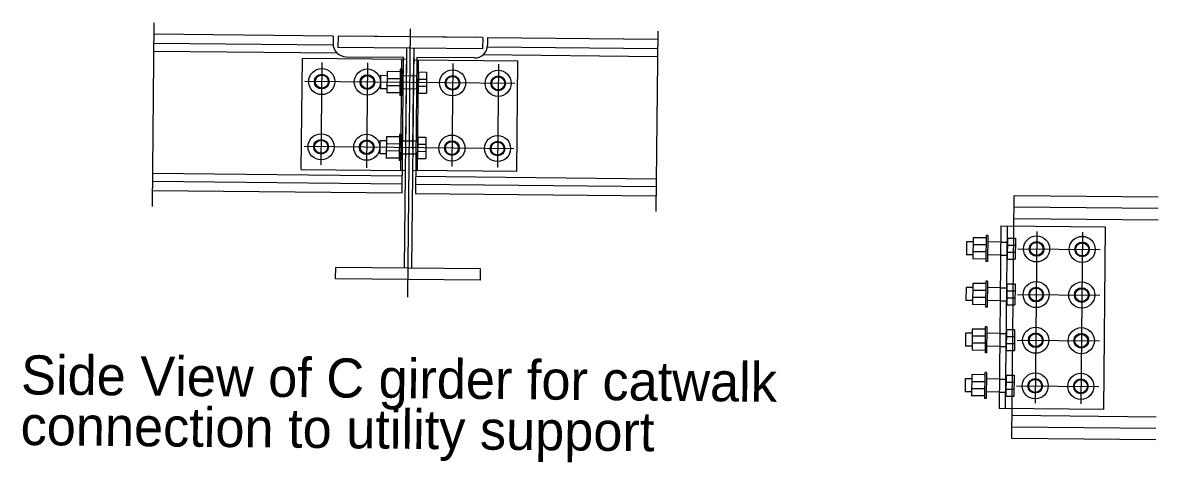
# Model space of a CAD drawing. Extents: x 632312 to 632885, y 378199 to 378534.
# Drawn here: x 632382.19 to 632389.45, y 378388.67 to 378391.48 of the extents above; entities that cross this region are included whole.
import ezdxf

# ---------------------------------------------------------------- set-up
doc = ezdxf.new("R2010")
doc.units = 0
for name, color, linetype in [('B_Boring', 7, 'Continuous'), ('R_Proposed Const Limits Cut', 7, 'Continuous'), ('R_Wall', 7, 'Continuous'), ('SHT_Dimensions', 7, 'Continuous'), ('USACE_Easement', 7, 'Continuous')]:
    doc.layers.add(name, color=color, linetype=linetype)

msp = doc.modelspace()

# ---------------------------------------------------------------- linework, layer by layer
at = {"layer": 'B_Boring'}
for p, q in [((632384.1753, 378391.3967), (632383.029, 378391.4081)), ((632384.1753, 378391.3967), (632384.1748, 378391.3488)), ((632384.2065, 378391.3964), (632384.2058, 378391.3239)), ((632385.1315, 378391.3872), (632384.2065, 378391.3964)), ((632385.1315, 378391.3872), (632385.1307, 378391.3147)), ((632385.1627, 378391.3869), (632385.1622, 378391.339)), ((632385.1627, 378391.3869), (632386.249, 378391.3761)), ((632384.1747, 378391.3384), (632383.0284, 378391.3498)), ((632385.1307, 378391.3147), (632384.2058, 378391.3239)), ((632384.632, 378389.9146), (632384.646, 378391.3195)), ((632384.6906, 378391.3191), (632384.6766, 378389.9141)), ((632385.1621, 378391.3286), (632386.2485, 378391.3178)), ((632383.9716, 378390.5445), (632383.9786, 378391.2528)), ((632384.6452, 378391.2462), (632383.9786, 378391.2528)), ((632384.2573, 378391.2646), (632384.6245, 378391.261)), ((632384.6069, 378390.5382), (632384.614, 378391.2465)), ((632384.6159, 378390.3923), (632384.6245, 378391.261)), ((632384.6898, 378391.2457), (632385.3565, 378391.2391)), ((632384.7108, 378391.2601), (632384.7022, 378390.3914)), ((632385.0781, 378391.2565), (632384.7108, 378391.2601)), ((632384.714, 378390.5371), (632384.7211, 378391.2454)), ((632385.3494, 378390.5308), (632385.3565, 378391.2391)), ((632384.5195, 378391.1693), (632384.5181, 378391.0339)), ((632384.6028, 378391.1685), (632384.5195, 378391.1693)), ((632384.6029, 378391.1841), (632384.6013, 378391.0175)), ((632384.6134, 378391.184), (632384.6029, 378391.1841)), ((632384.6134, 378391.184), (632384.6117, 378391.0173)), ((632384.7203, 378391.1673), (632384.7189, 378391.0319)), ((632384.7203, 378391.1673), (632384.7724, 378391.1668)), ((632384.7724, 378391.1668), (632384.771, 378391.0314)), ((632384.4775, 378391.1437), (632384.4767, 378391.0604)), ((632384.5192, 378391.1433), (632384.4775, 378391.1437)), ((632384.6023, 378391.1233), (632384.519, 378391.1242)), ((632384.7198, 378391.1222), (632384.7719, 378391.1217)), ((632384.5184, 378391.0599), (632384.4767, 378391.0604)), ((632384.6014, 378391.0331), (632384.5181, 378391.0339)), ((632384.6019, 378391.0782), (632384.5186, 378391.079)), ((632384.6117, 378391.0173), (632384.6013, 378391.0175)), ((632384.7189, 378391.0319), (632384.771, 378391.0314)), ((632384.7194, 378391.077), (632384.7715, 378391.0765)), ((632384.4734, 378390.727), (632384.4726, 378390.6437)), ((632384.5151, 378390.7266), (632384.4734, 378390.727)), ((632384.5153, 378390.7527), (632384.514, 378390.6173)), ((632384.5986, 378390.7518), (632384.5153, 378390.7527)), ((632384.5988, 378390.7675), (632384.5971, 378390.6008)), ((632384.6092, 378390.7674), (632384.5988, 378390.7675)), ((632384.6092, 378390.7674), (632384.6076, 378390.6007)), ((632384.7162, 378390.7507), (632384.7148, 378390.6153)), ((632384.7162, 378390.7507), (632384.7682, 378390.7501)), ((632384.7682, 378390.7501), (632384.7669, 378390.6148)), ((632384.5977, 378390.6616), (632384.5144, 378390.6624)), ((632384.5982, 378390.7067), (632384.5149, 378390.7075)), ((632384.7153, 378390.6604), (632384.7673, 378390.6599)), ((632384.7157, 378390.7055), (632384.7678, 378390.705)), ((632384.5142, 378390.6433), (632384.4726, 378390.6437)), ((632384.5973, 378390.6164), (632384.514, 378390.6173)), ((632384.6076, 378390.6007), (632384.5971, 378390.6008)), ((632384.7148, 378390.6153), (632384.7669, 378390.6148)), ((632383.9716, 378390.5445), (632384.6382, 378390.5379)), ((632385.3494, 378390.5308), (632384.6828, 378390.5375)), ((632384.6164, 378390.4506), (632383.0196, 378390.4665)), ((632384.7027, 378390.4497), (632386.2397, 378390.4345)), ((632384.6159, 378390.3923), (632383.019, 378390.4082)), ((632384.7022, 378390.3914), (632386.2391, 378390.3761)), ((632388.5133, 378388.8256), (632388.5287, 378390.3756)), ((632389.4491, 378390.3664), (632388.5287, 378390.3756)), ((632389.4483, 378390.2939), (632388.528, 378390.3031)), ((632388.4435, 378390.1847), (632388.4319, 378389.0181)), ((632388.4435, 378390.1847), (632389.1101, 378390.1781)), ((632388.4735, 378389.0177), (632388.4851, 378390.1843)), ((632389.1101, 378390.1781), (632389.0985, 378389.0115)), ((632388.2237, 378390.0828), (632388.2229, 378389.9994)), ((632388.2654, 378390.0823), (632388.2237, 378390.0828)), ((632388.2656, 378390.1084), (632388.2643, 378389.973)), ((632388.349, 378390.1075), (632388.2656, 378390.1084)), ((632388.3491, 378390.1232), (632388.3475, 378389.9565)), ((632388.3595, 378390.1231), (632388.3491, 378390.1232)), ((632388.3595, 378390.1231), (632388.3579, 378389.9564)), ((632388.4424, 378390.0806), (632388.3591, 378390.0814)), ((632388.4844, 378390.1062), (632388.5364, 378390.1057)), ((632388.5364, 378390.1057), (632388.5351, 378389.9703)), ((632388.2645, 378389.999), (632388.2229, 378389.9994)), ((632388.3481, 378390.0173), (632388.2647, 378390.0181)), ((632388.3485, 378390.0624), (632388.2652, 378390.0632)), ((632388.4416, 378389.9973), (632388.3583, 378389.9981)), ((632388.4835, 378390.0159), (632388.5356, 378390.0154)), ((632388.4839, 378390.0611), (632388.536, 378390.0606)), ((632388.3476, 378389.9722), (632388.2643, 378389.973)), ((632388.3579, 378389.9564), (632388.3475, 378389.9565)), ((632388.483, 378389.9708), (632388.5351, 378389.9703)), ((632384.1911, 378389.8465), (632384.1918, 378389.919)), ((632385.1168, 378389.9098), (632384.1918, 378389.919)), ((632385.116, 378389.8373), (632385.1168, 378389.9098)), ((632385.116, 378389.8373), (632384.1911, 378389.8465)), ((632388.2208, 378389.7911), (632388.22, 378389.7078)), ((632388.2625, 378389.7907), (632388.2208, 378389.7911)), ((632388.2627, 378389.8167), (632388.2614, 378389.6813)), ((632388.3461, 378389.8159), (632388.2627, 378389.8167)), ((632388.3462, 378389.8315), (632388.3446, 378389.6649)), ((632388.3566, 378389.8314), (632388.3462, 378389.8315)), ((632388.3566, 378389.8314), (632388.355, 378389.6648)), ((632388.4395, 378389.7889), (632388.3562, 378389.7898)), ((632388.4815, 378389.8145), (632388.5335, 378389.814)), ((632388.5335, 378389.814), (632388.5322, 378389.6786)), ((632388.2616, 378389.7074), (632388.22, 378389.7078)), ((632388.3452, 378389.7256), (632388.2618, 378389.7265)), ((632388.3456, 378389.7708), (632388.2623, 378389.7716)), ((632388.4387, 378389.7056), (632388.3554, 378389.7064)), ((632388.4806, 378389.7243), (632388.5327, 378389.7238)), ((632388.481, 378389.7694), (632388.5331, 378389.7689)), ((632388.3447, 378389.6805), (632388.2614, 378389.6813)), ((632388.355, 378389.6648), (632388.3446, 378389.6649)), ((632388.4801, 378389.6792), (632388.5322, 378389.6786)), ((632388.2179, 378389.4995), (632388.2171, 378389.4161)), ((632388.2596, 378389.499), (632388.2179, 378389.4995)), ((632388.2598, 378389.5251), (632388.2585, 378389.3897)), ((632388.3432, 378389.5242), (632388.2598, 378389.5251)), ((632388.3433, 378389.5399), (632388.3417, 378389.3732)), ((632388.3537, 378389.5398), (632388.3433, 378389.5399)), ((632388.3537, 378389.5398), (632388.3521, 378389.3731)), ((632388.4366, 378389.4973), (632388.3533, 378389.4981)), ((632388.4786, 378389.5229), (632388.5306, 378389.5224)), ((632388.5306, 378389.5224), (632388.5293, 378389.387)), ((632388.2587, 378389.4157), (632388.2171, 378389.4161)), ((632388.3423, 378389.434), (632388.2589, 378389.4348)), ((632388.3427, 378389.4791), (632388.2594, 378389.4799)), ((632388.4358, 378389.4139), (632388.3525, 378389.4148)), ((632388.4777, 378389.4326), (632388.5298, 378389.4321)), ((632388.4781, 378389.4778), (632388.5302, 378389.4772)), ((632388.3418, 378389.3888), (632388.2585, 378389.3897)), ((632388.3521, 378389.3731), (632388.3417, 378389.3732)), ((632388.4772, 378389.3875), (632388.5293, 378389.387)), ((632388.215, 378389.2078), (632388.2142, 378389.1245)), ((632388.2567, 378389.2074), (632388.215, 378389.2078)), ((632388.2569, 378389.2334), (632388.2556, 378389.098)), ((632388.3403, 378389.2326), (632388.2569, 378389.2334)), ((632388.3404, 378389.2482), (632388.3388, 378389.0816)), ((632388.3508, 378389.2481), (632388.3404, 378389.2482)), ((632388.3508, 378389.2481), (632388.3492, 378389.0815)), ((632388.4337, 378389.2056), (632388.3504, 378389.2065)), ((632388.4757, 378389.2312), (632388.5277, 378389.2307)), ((632388.5277, 378389.2307), (632388.5264, 378389.0953)), ((632388.2558, 378389.1241), (632388.2142, 378389.1245)), ((632388.3394, 378389.1423), (632388.256, 378389.1432)), ((632388.3398, 378389.1875), (632388.2565, 378389.1883)), ((632388.4329, 378389.1223), (632388.3496, 378389.1231)), ((632388.4748, 378389.141), (632388.5269, 378389.1405)), ((632388.4752, 378389.1861), (632388.5273, 378389.1856)), ((632388.3389, 378389.0972), (632388.2556, 378389.098)), ((632388.3492, 378389.0815), (632388.3388, 378389.0816)), ((632388.4743, 378389.0958), (632388.5264, 378389.0953)), ((632389.0985, 378389.0115), (632388.4319, 378389.0181)), ((632389.4344, 378388.889), (632388.514, 378388.8981)), ((632389.4337, 378388.8165), (632388.5133, 378388.8256))]:
    msp.add_line(p, q, dxfattribs=at)
for centre in [(632384.1021, 378391.1058), (632384.3938, 378391.1029), (632384.9384, 378391.0974), (632385.23, 378391.0945), (632384.098, 378390.6891), (632384.3896, 378390.6862), (632384.9342, 378390.6808), (632385.2259, 378390.6779), (632388.6712, 378390.0366), (632388.9628, 378390.0337), (632388.6683, 378389.745), (632388.9599, 378389.7421), (632388.6654, 378389.4533), (632388.957, 378389.4504), (632388.6625, 378389.1617), (632388.9541, 378389.1588)]:
    msp.add_circle(centre, 0.0469, dxfattribs=at)
for centre, start, end in [((632384.2581, 378391.348), 179.43036, 269.43036), ((632385.0789, 378391.3398), 269.43036, 359.43036)]:
    msp.add_arc(centre, 0.0833, start, end, dxfattribs=at)
at = {"layer": 'R_Proposed Const Limits Cut'}
for p, q in [((632384.2012, 378391.2871), (632383.0279, 378391.2987)), ((632385.1346, 378391.2778), (632386.2479, 378391.2667)), ((632384.72, 378391.1413), (632384.6129, 378391.1423)), ((632384.7192, 378391.0579), (632384.6121, 378391.059)), ((632384.7159, 378390.7246), (632384.6088, 378390.7257)), ((632384.7151, 378390.6413), (632384.608, 378390.6424)), ((632384.6169, 378390.5016), (632383.0201, 378390.5175)), ((632384.7033, 378390.5008), (632386.2402, 378390.4855)), ((632389.4476, 378390.2206), (632388.5273, 378390.2297)), ((632388.4424, 378390.0806), (632388.4841, 378390.0802)), ((632388.4416, 378389.9973), (632388.4833, 378389.9968)), ((632388.4395, 378389.7889), (632388.4812, 378389.7885)), ((632388.4387, 378389.7056), (632388.4804, 378389.7052)), ((632388.4366, 378389.4973), (632388.4783, 378389.4969)), ((632388.4358, 378389.4139), (632388.4775, 378389.4135)), ((632388.4337, 378389.2056), (632388.4754, 378389.2052)), ((632388.4329, 378389.1223), (632388.4746, 378389.1219)), ((632389.4351, 378388.9623), (632388.5148, 378388.9715))]:
    msp.add_line(p, q, dxfattribs=at)
for centre, radius in [((632384.1021, 378391.1058), 0.0833), ((632384.3938, 378391.1029), 0.0833), ((632384.9384, 378391.0974), 0.0833), ((632385.23, 378391.0945), 0.0833), ((632384.1021, 378391.1058), 0.0417), ((632384.3938, 378391.1029), 0.0417), ((632384.9384, 378391.0974), 0.0417), ((632385.23, 378391.0945), 0.0417), ((632384.098, 378390.6891), 0.0833), ((632384.098, 378390.6891), 0.0417), ((632384.3896, 378390.6862), 0.0833), ((632384.3896, 378390.6862), 0.0417), ((632384.9342, 378390.6808), 0.0833), ((632384.9342, 378390.6808), 0.0417), ((632385.2259, 378390.6779), 0.0833), ((632385.2259, 378390.6779), 0.0417), ((632388.6712, 378390.0366), 0.0833), ((632388.6712, 378390.0366), 0.0417), ((632388.9628, 378390.0337), 0.0833), ((632388.9628, 378390.0337), 0.0417), ((632388.6683, 378389.745), 0.0833), ((632388.6683, 378389.745), 0.0417), ((632388.9599, 378389.7421), 0.0833), ((632388.9599, 378389.7421), 0.0417), ((632388.6654, 378389.4533), 0.0833), ((632388.6654, 378389.4533), 0.0417), ((632388.957, 378389.4504), 0.0833), ((632388.957, 378389.4504), 0.0417), ((632388.6625, 378389.1617), 0.0833), ((632388.6625, 378389.1617), 0.0417), ((632388.9541, 378389.1588), 0.0833), ((632388.9541, 378389.1588), 0.0417)]:
    msp.add_circle(centre, radius, dxfattribs=at)
at = {"layer": 'R_Wall'}
for p, q in [((632384.6524, 378389.7292), (632384.6695, 378391.4437)), ((632384.1034, 378391.2285), (632384.0969, 378390.5743)), ((632384.395, 378391.2256), (632384.3883, 378390.5546)), ((632384.9396, 378391.2202), (632384.9331, 378390.5637)), ((632385.2312, 378391.2173), (632385.2247, 378390.5577)), ((632385.3356, 378391.0935), (632383.9951, 378391.1068)), ((632385.3297, 378390.6769), (632383.9906, 378390.6902)), ((632388.6723, 378390.1476), (632388.6614, 378389.0507)), ((632388.9639, 378390.1447), (632388.953, 378389.0478)), ((632388.5519, 378390.0378), (632389.0785, 378390.0326)), ((632388.549, 378389.7462), (632389.0756, 378389.7409)), ((632388.5461, 378389.4545), (632389.0727, 378389.4493)), ((632388.5432, 378389.1629), (632389.0698, 378389.1576))]:
    msp.add_line(p, q, dxfattribs=at)
at = {"layer": 'SHT_Dimensions'}
for p, q in [((632383.0297, 378391.4817), (632383.018, 378390.3077)), ((632385.0856, 378391.3877), (632384.2523, 378391.3959)), ((632386.2495, 378391.4272), (632386.2381, 378390.2757)), ((632384.6395, 378390.6733), (632384.6453, 378391.2562)), ((632384.6841, 378390.6729), (632384.6899, 378391.2557)), ((632388.4844, 378390.1062), (632388.483, 378389.9708)), ((632388.4815, 378389.8145), (632388.4801, 378389.6792)), ((632388.4786, 378389.5229), (632388.4772, 378389.3875)), ((632388.4757, 378389.2312), (632388.4743, 378389.0958))]:
    msp.add_line(p, q, dxfattribs=at)

# ---------------------------------------------------------------- texts
at = {"layer": 'USACE_Easement'}
for s, p in [('Side View of C girder for catwalk ', (632382.1795, 378389.1077)), ('connection to utility support', (632382.1763, 378388.7842))]:
    msp.add_text(s, height=0.25, rotation=359.43036, dxfattribs=at).set_placement(p)

doc.saveas('drawing.dxf')
